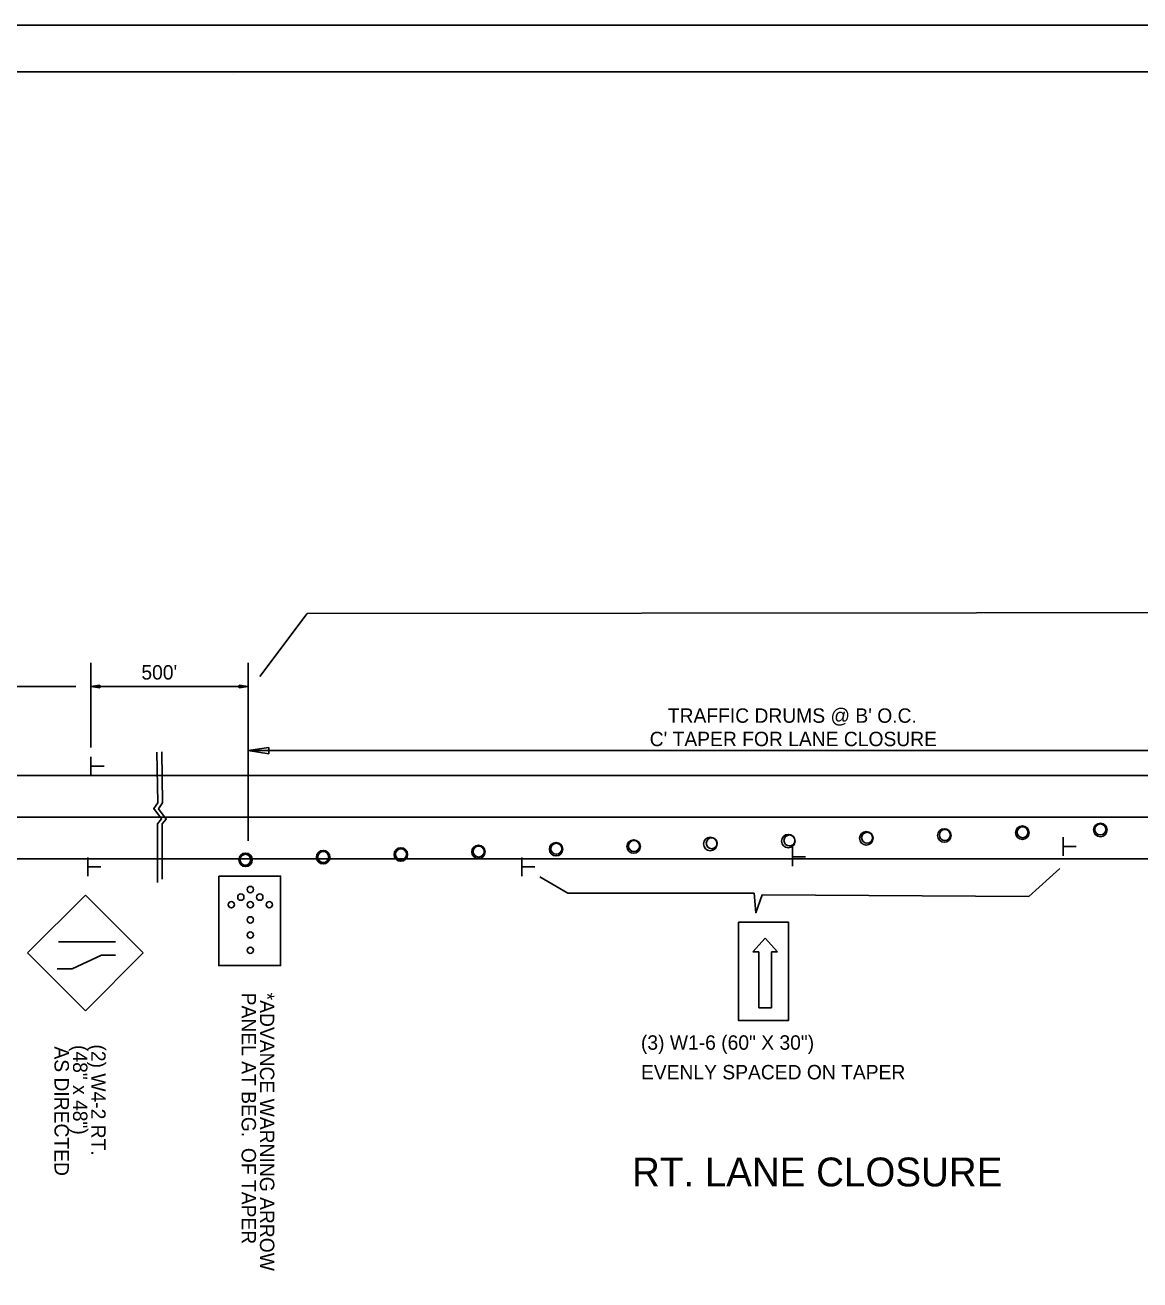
# Model space of a CAD drawing. Extents: x 1374897 to 1375063, y 381144 to 381251.
# Drawn here: x 1374970.4 to 1375016.8, y 381198.7 to 381251 of the extents above; entities that cross this region are included whole.
import ezdxf

# ---------------------------------------------------------------- set-up
doc = ezdxf.new("R2010")
doc.units = 0
for name, color, linetype in [('Default', 7, 'Continuous'), ('R_Border', 7, 'Continuous'), ('R_No Plot', 7, 'Continuous')]:
    doc.layers.add(name, color=color, linetype=linetype)

msp = doc.modelspace()

# ---------------------------------------------------------------- linework, layer by layer
at = {"layer": 'Default'}
for p, q in [((1374973.108, 381224.39), (1374973.108, 381220.869)), ((1374979.655, 381224.39), (1374979.655, 381216.976)), ((1374967.257, 381223.411), (1374972.476, 381223.411)), ((1374973.483, 381223.468), (1374973.108, 381223.411)), ((1374973.108, 381223.411), (1374979.655, 381223.411)), ((1374973.483, 381223.355), (1374973.108, 381223.411)), ((1374973.483, 381223.458), (1374973.171, 381223.411)), ((1374973.483, 381223.364), (1374973.171, 381223.411)), ((1374973.483, 381223.449), (1374973.235, 381223.411)), ((1374973.483, 381223.374), (1374973.235, 381223.411)), ((1374973.483, 381223.439), (1374973.298, 381223.411)), ((1374973.483, 381223.383), (1374973.298, 381223.411)), ((1374973.483, 381223.43), (1374973.361, 381223.411)), ((1374973.483, 381223.393), (1374973.361, 381223.411)), ((1374973.483, 381223.42), (1374973.424, 381223.411)), ((1374973.483, 381223.402), (1374973.424, 381223.411)), ((1374973.483, 381223.355), (1374973.483, 381223.468)), ((1374979.28, 381223.468), (1374979.655, 381223.411)), ((1374979.28, 381223.468), (1374979.28, 381223.355)), ((1374979.28, 381223.458), (1374979.593, 381223.411)), ((1374979.28, 381223.449), (1374979.528, 381223.411)), ((1374979.28, 381223.439), (1374979.466, 381223.411)), ((1374979.28, 381223.429), (1374979.402, 381223.411)), ((1374979.28, 381223.42), (1374979.34, 381223.411)), ((1374979.28, 381223.355), (1374979.655, 381223.411)), ((1374979.28, 381223.393), (1374979.402, 381223.411)), ((1374979.28, 381223.374), (1374979.528, 381223.411)), ((1374979.28, 381223.364), (1374979.593, 381223.411)), ((1374979.28, 381223.383), (1374979.466, 381223.411)), ((1374979.28, 381223.402), (1374979.34, 381223.411)), ((1374979.655, 381222.108), (1374979.655, 381218.587)), ((1374979.655, 381220.74), (1374980.525, 381220.87)), ((1375024.856, 381220.74), (1374979.655, 381220.74)), ((1374980.525, 381220.609), (1374979.655, 381220.74)), ((1374980.525, 381220.87), (1374980.525, 381220.609)), ((1374973.108, 381219.696), (1374973.108, 381220.478)), ((1374963.663, 381219.7), (1374979.655, 381219.7)), ((1374973.12, 381220.085), (1374973.654, 381220.085)), ((1374979.655, 381219.7), (1375050.934, 381219.7)), ((1374963.663, 381217.961), (1374979.655, 381217.961)), ((1374979.655, 381217.961), (1375050.934, 381217.961)), ((1375013.6, 381216.353), (1375013.6, 381217.136)), ((1375002.329, 381215.927), (1375002.329, 381216.709)), ((1375013.611, 381216.742), (1375014.145, 381216.742)), ((1374963.663, 381216.223), (1374979.655, 381216.223)), ((1374972.982, 381215.505), (1374972.982, 381216.287)), ((1374979.655, 381216.223), (1375050.934, 381216.223)), ((1374991.058, 381215.5), (1374991.058, 381216.283)), ((1375002.34, 381216.316), (1375002.874, 381216.316)), ((1374972.993, 381215.894), (1374973.527, 381215.894)), ((1374991.07, 381215.889), (1374991.604, 381215.889)), ((1374972.876, 381214.719), (1374970.466, 381212.309)), ((1374972.876, 381214.719), (1374975.285, 381212.309)), ((1375000.675, 381212.352), (1375001.194, 381212.921)), ((1375001.194, 381212.921), (1375001.713, 381212.352)), ((1374970.466, 381212.309), (1374972.876, 381209.9)), ((1374971.759, 381212.773), (1374974.13, 381212.773)), ((1374975.285, 381212.309), (1374972.876, 381209.9)), ((1375000.935, 381212.352), (1375000.675, 381212.352)), ((1375000.935, 381210.022), (1375000.935, 381212.352)), ((1375001.454, 381210.022), (1375001.454, 381212.352)), ((1375001.454, 381212.352), (1375001.713, 381212.352)), ((1374972.322, 381211.649), (1374973.546, 381212.211)), ((1374973.546, 381212.211), (1374974.13, 381212.211)), ((1374971.708, 381211.649), (1374972.322, 381211.649)), ((1375000.935, 381210.022), (1375001.454, 381210.022))]:
    msp.add_line(p, q, dxfattribs=at)
for points in [[(1374980.142, 381223.824), (1374982.117, 381226.442), (1375023.943, 381226.49), (1375024.749, 381228.909), (1375024.822, 381226.525), (1375049.49, 381226.192), (1375050.632, 381223.594)], [(1374975.859, 381220.67), (1374975.891, 381218.567), (1374975.728, 381218.325), (1374976.045, 381217.892), (1374975.878, 381217.692), (1374975.877, 381215.247)], [(1374976.058, 381220.689), (1374976.09, 381218.558), (1374975.928, 381218.317), (1374976.244, 381217.884), (1374976.078, 381217.684), (1374976.077, 381215.387)], [(1374991.81, 381215.479), (1374992.969, 381214.798), (1375000.734, 381214.798), (1375000.802, 381213.98), (1375001.074, 381214.73), (1375012.178, 381214.662), (1375013.472, 381215.82)]]:
    msp.add_lwpolyline(points, dxfattribs=at)
for points in [[(1374978.43, 381215.508), (1374978.43, 381211.784), (1374981.006, 381211.784), (1374981.006, 381215.508)], [(1375000.081, 381213.587), (1375000.081, 381209.501), (1375002.171, 381209.501), (1375002.171, 381213.587)]]:
    msp.add_lwpolyline(points, close=True, dxfattribs=at)
for centre, radius in [((1375011.907, 381217.316), 0.281), ((1375011.916, 381217.337), 0.229), ((1375015.157, 381217.432), 0.281), ((1375015.153, 381217.452), 0.229), ((1374995.717, 381216.74), 0.281), ((1374998.906, 381216.85), 0.281), ((1374998.969, 381216.878), 0.229), ((1375002.156, 381216.967), 0.281), ((1375002.206, 381216.993), 0.229), ((1375005.407, 381217.083), 0.281), ((1375005.442, 381217.107), 0.229), ((1375008.657, 381217.199), 0.281), ((1375008.679, 381217.222), 0.229), ((1374982.783, 381216.297), 0.281), ((1374982.785, 381216.305), 0.229), ((1374986.017, 381216.408), 0.281), ((1374986.022, 381216.419), 0.229), ((1374989.25, 381216.518), 0.281), ((1374989.259, 381216.534), 0.229), ((1374992.484, 381216.629), 0.281), ((1374992.495, 381216.649), 0.229), ((1374995.732, 381216.763), 0.229), ((1374979.55, 381216.186), 0.281), ((1374979.536, 381216.191), 0.229), ((1374979.548, 381216.19), 0.229), ((1374979.747, 381214.95), 0.131), ((1374978.958, 381214.318), 0.131), ((1374979.353, 381214.634), 0.131), ((1374979.747, 381214.318), 0.131), ((1374980.142, 381214.634), 0.131), ((1374980.537, 381214.318), 0.131), ((1374979.747, 381213.686), 0.131), ((1374979.747, 381213.053), 0.131), ((1374979.747, 381212.421), 0.131)]:
    msp.add_circle(centre, radius, dxfattribs=at)
at = {"layer": 'R_Border'}
for p, q in [((1374902.775, 381249.01), (1375060.865, 381249.01)), ((1374979.035, 381248.88), (1374979.035, 381248.88)), ((1374979.035, 381248.88), (1374979.035, 381248.88))]:
    msp.add_line(p, q, dxfattribs=at)
at = {"layer": 'R_No Plot'}
msp.add_line((1374896.575, 381250.958), (1375063.241, 381250.958), dxfattribs=at)
for points in [[(1374896.571, 381250.958), (1375063.241, 381250.958), (1375063.241, 381144.289), (1374896.571, 381144.289)], [(1375019.735, 381249.01), (1375029.545, 381249.01), (1375029.545, 381244.07), (1375037.601, 381244.07), (1375049.201, 381244.07), (1375049.201, 381231.904), (1375060.865, 381231.904), (1375060.865, 381146.28), (1374902.775, 381146.28), (1374902.775, 381249.01)]]:
    msp.add_lwpolyline(points, close=True, dxfattribs=at)

# ---------------------------------------------------------------- texts
at = {"layer": 'Default'}
for s, height, p in [("500'", 0.6, (1374975.209, 381223.697)), ("TRAFFIC DRUMS @ B' O.C.", 0.6, (1374997.139, 381221.896)), ("C' TAPER FOR LANE CLOSURE", 0.6, (1374996.383, 381220.922)), ('RT. LANE CLOSURE', 1.2, (1374995.648, 381202.586))]:
    msp.add_text(s, height=height, dxfattribs=at).set_placement(p)
for s, rotation, p in [('PANEL AT BEG.  OF TAPER', 270, (1374979.384, 381210.654)), ('*ADVANCE WARNING ARROW', 270, (1374980.148, 381210.654)), ('(3) W1-6 (60" X 30")', 0.0075, (1374996.019, 381208.277)), ('AS DIRECTED ', 270, (1374971.59, 381208.415)), ('(48" x 48")', 270, (1374972.362, 381208.472)), ('(2) W4-2 RT.', 270, (1374973.119, 381208.497)), ('EVENLY SPACED ON TAPER', 0.0075, (1374996.019, 381207.042))]:
    msp.add_text(s, height=0.6, rotation=rotation, dxfattribs=at).set_placement(p)

doc.saveas('drawing.dxf')
